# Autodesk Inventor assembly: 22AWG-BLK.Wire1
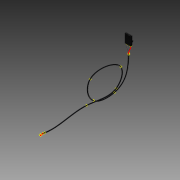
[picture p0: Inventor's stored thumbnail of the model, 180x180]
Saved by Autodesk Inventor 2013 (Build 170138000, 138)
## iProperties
ParentFileIdentifier: 5|1|0|0|176|2|0|0|80|0|65|0|84|0|72|0|83|0|59|0|67|0|58|0|92|0|80|0|114|0|111|0|103|0|114|0|97|0|109|0|32|0|70|0|105|0|108|0|101|0|115|0|92|0|65|0|117|0|116|0|1
Part Number: 22AWG-BLK.Wire1
Material: Default
Description: 22AWG-BLK
Stock Number: 22AWG-BLK
Density: 1 g/cm^3
Part Number: 22AWG-RED.Wire2
Description: 22AWG-RED
Stock Number: 22AWG-RED
Created: 2007-02
Part Number: Cooling Fan Harness
Document SubType Name: Assembly
Designer: floress
Mass: 0.263499 g
Surface Area: 8.95077 cm^2
Volume: 0.263499 cm^3
HarnessSettings: <HarnessSettings><Defaults><Segments><Diameter value="0.200 in" fromwires="True"/><Offset value="0.100 in"/><ColorStyle value="Blue"/><RoundUp value=""/><BendRa
CableDummyParamRefKey: Key:16|2|0|0|16|0|0|0|250|0|0|0|0|0|0|0|129|0|0|0|0|0|0|0|Level:1
Author: floress
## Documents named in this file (3)
- Z:\_DATEN\Personal Computer\Aip\Cooling Fan Harness.iam
- Z:\_DATEN\Personal Computer\Aip\Cooling Fan Harness.ipt
- Z:\_DATEN\Personal Computer\Aip\Fan Connector.ipt
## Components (4 placed, 4 different names)
1. Cooling Fan Harness
2. Fan Connector:1
3. HA_VC_123:1
4. HA_VC_126:1
